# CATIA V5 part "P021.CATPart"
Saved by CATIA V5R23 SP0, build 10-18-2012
Part number: 05-LICP-T02-E-S05-P021
Definition: Plateau Embrayage
Description: Plateau Embrayage
Bounding box of the stored display mesh (mm): x -27 to 0, y -39.998 to 39.998, z -40 to 40
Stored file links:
  C:\wamp\www\COURS\CONCEPTION GMP1\TITRE 02-SEMESTRE 2\03-TP7-PRESSE MECANIQUE\eleve\P021.CATPart
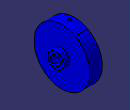
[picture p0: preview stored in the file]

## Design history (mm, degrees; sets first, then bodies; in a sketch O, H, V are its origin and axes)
Body1 (main body)
  Sketch1 on zx-plane, origin (0, 0, 0), H (-1, 0, 0), V (0, 0, 1)
    point P1 (0, 7)
    line L1 (0, 7) -> (0, 11)
    line L2 (0, 11) -> (9, 11)
    line L3 (9, 11) -> (9, 40)
    line L4 (9, 40) -> (27, 40)
    line L5 (27, 40) -> (27, 22)
    line L6 (27, 22) -> (25, 22)
    line L7 (25, 22) -> (25, 7)
    line L8 (25, 7) -> (0, 7)
    distance L8 H = 7
    distance L2 L8 = 4
    distance L3 L1 = 9
    distance L4 H = 40
    length L6 = 2
    distance L5 L3 = 18
    distance L6 L4 = 18
    coincidence: P1 V
    vertical: L1 V, L3 V, L5 V, L7 V
    horizontal: L2 H, L4 H, L6 H, L8 H
  Shaft1: profile Sketch1, axis Sketch1.H, angle 360
  Sketch2 on face of Shaft1, origin (-27, 0, 0), H (0, -1, 0), V (0, 0, 1)
    circle A1 centre (-31.5, 0) radius 5.5
    point P1 (-31.5, 0)
    radius A1 = 5.5
    distance P1 V = 31.5
    coincidence: P1 H
  Pocket1: profile Sketch2, direction (1, 0, 0), length 17
  Sketch3 on xy-plane, origin (0, 0, 0), H (1, 0, 0), V (0, 1, 0)
    circle A1 centre (-20, 0) radius 2.5
    point P1 (-20, 0)
    point P2 (-17.5, 0)
    reference intersected line E1 (-27, -40) -> (-27, -22) from face of Shaft1
    distance P1 E1 = 7
    radius A1 = 2.5
    coincidence: P1 H, A1 P2, P2 H
  Pocket2: profile Sketch3, direction (0, 0, -1), through (limit type 3), opposite side through (limit type 3)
